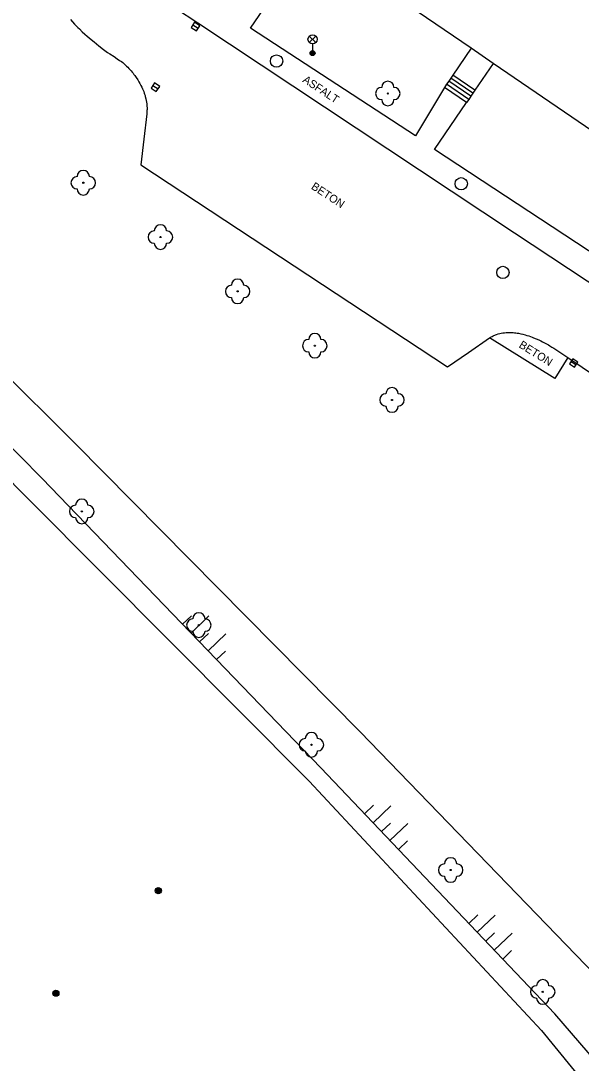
# Model space of a CAD drawing. Extents: x -539515 to -538098, y -1182060 to -1180157.
# Drawn here: x -538972.2 to -538926.7, y -1181508.2 to -1181423.5 of the extents above; entities that cross this region are included whole.
import ezdxf

# ---------------------------------------------------------------- set-up
doc = ezdxf.new("R2010")
doc.units = 0
for name, color, linetype in [('Vrstva 10', 7, 'Continuous'), ('Vrstva 11', 7, 'Continuous'), ('Vrstva 14', 7, 'Continuous'), ('Vrstva 15', 7, 'Continuous'), ('Vrstva 22', 7, 'Continuous'), ('Vrstva 23', 7, 'Continuous'), ('Vrstva 25', 7, 'Continuous'), ('Vrstva 27', 7, 'Continuous'), ('Vrstva 33', 7, 'Continuous'), ('Vrstva 40', 7, 'Continuous'), ('Vrstva 5', 7, 'Continuous')]:
    doc.layers.add(name, color=color, linetype=linetype)

msp = doc.modelspace()

# ---------------------------------------------------------------- linework, layer by layer
at = {"layer": 'Vrstva 10'}
for p, q in [((-538944.966, -1181432.217), (-538957.83, -1181423.69)), ((-538932.1, -1181440.742), (-538944.966, -1181432.217)), ((-538962.49, -1181435.19), (-538937.53, -1181451.61)), ((-538923.52, -1181446.42), (-538932.1, -1181440.742))]:
    msp.add_line(p, q, dxfattribs=at)
for points in [[(-538957.83, -1181423.69), (-538959.65, -1181422.485)], [(-538968.209, -1181423.401), (-538968.047, -1181423.582), (-538967.88, -1181423.76), (-538967.739, -1181423.904), (-538967.607, -1181424.036), (-538967.481, -1181424.158), (-538967.244, -1181424.379), (-538967.034, -1181424.568), (-538966.85, -1181424.73), (-538966.523, -1181425.007), (-538966.276, -1181425.211), (-538965.903, -1181425.514), (-538965.527, -1181425.817), (-538965.413, -1181425.906), (-538965.305, -1181425.986), (-538965.202, -1181426.057), (-538965.007, -1181426.187), (-538964.66, -1181426.407), (-538964.399, -1181426.574), (-538964.204, -1181426.706), (-538964.06, -1181426.811), (-538963.953, -1181426.894), (-538963.873, -1181426.959), (-538963.756, -1181427.061), (-538963.64, -1181427.17), (-538963.54, -1181427.271), (-538963.445, -1181427.37), (-538963.355, -1181427.468), (-538963.27, -1181427.565), (-538963.19, -1181427.66), (-538963.113, -1181427.753)], [(-538963.113, -1181427.753), (-538963.041, -1181427.845), (-538962.974, -1181427.935), (-538962.847, -1181428.112), (-538962.735, -1181428.281), (-538962.635, -1181428.442), (-538962.548, -1181428.596), (-538962.47, -1181428.741), (-538962.402, -1181428.879), (-538962.343, -1181429.01), (-538962.29, -1181429.133), (-538962.245, -1181429.25), (-538962.205, -1181429.36), (-538962.17, -1181429.463), (-538962.14, -1181429.561), (-538962.114, -1181429.652), (-538962.071, -1181429.825), (-538962.04, -1181429.977), (-538962.018, -1181430.111), (-538962.002, -1181430.228), (-538961.991, -1181430.33), (-538961.984, -1181430.42), (-538961.977, -1181430.577), (-538961.977, -1181430.696), (-538961.979, -1181430.784), (-538961.987, -1181430.917), (-538962, -1181431.05), (-538962.245, -1181433.12), (-538962.49, -1181435.19)], [(-538937.53, -1181451.61), (-538935.82, -1181450.435), (-538934.11, -1181449.26), (-538934.041, -1181449.215), (-538933.972, -1181449.172), (-538933.904, -1181449.134), (-538933.835, -1181449.098), (-538933.766, -1181449.064), (-538933.698, -1181449.034), (-538933.629, -1181449.006), (-538933.561, -1181448.981), (-538933.425, -1181448.936), (-538933.291, -1181448.9), (-538933.158, -1181448.872), (-538933.028, -1181448.85), (-538932.9, -1181448.834), (-538932.774, -1181448.823), (-538932.651, -1181448.817), (-538932.531, -1181448.816), (-538932.414, -1181448.817), (-538932.3, -1181448.823), (-538932.189, -1181448.831), (-538932.08, -1181448.841), (-538931.975, -1181448.854), (-538931.873, -1181448.869), (-538931.773, -1181448.885), (-538931.58, -1181448.922), (-538931.4, -1181448.964), (-538931.23, -1181449.008), (-538931.071, -1181449.054), (-538930.923, -1181449.101), (-538930.785, -1181449.147), (-538930.656, -1181449.194), (-538930.536, -1181449.24), (-538930.313, -1181449.331), (-538930.121, -1181449.415), (-538929.955, -1181449.493), (-538929.813, -1181449.563), (-538929.69, -1181449.626), (-538929.479, -1181449.74), (-538929.325, -1181449.828), (-538929.213, -1181449.895), (-538929.049, -1181449.997), (-538928.89, -1181450.1)], [(-538928.89, -1181450.1), (-538927.757, -1181450.856), (-538925.412, -1181452.42), (-538921.935, -1181454.74), (-538918.458, -1181457.06)]]:
    msp.add_lwpolyline(points, dxfattribs=at)
at = {"layer": 'Vrstva 11'}
for p, q in [((-538953.56, -1181424.08), (-538950.761, -1181419.977)), ((-538940.13, -1181432.83), (-538953.56, -1181424.08)), ((-538935.643, -1181429.63), (-538937.441, -1181428.404)), ((-538935.474, -1181429.382), (-538937.272, -1181428.156)), ((-538935.305, -1181429.134), (-538937.103, -1181427.908)), ((-538937.78, -1181428.9), (-538940.13, -1181432.83)), ((-538935.982, -1181430.126), (-538937.78, -1181428.9)), ((-538935.812, -1181429.878), (-538937.61, -1181428.652)), ((-538938.59, -1181433.95), (-538935.982, -1181430.126)), ((-538925.14, -1181442.78), (-538938.59, -1181433.95)), ((-538928.82, -1181452.56), (-538934.11, -1181449.26)), ((-538927.757, -1181450.856), (-538928.82, -1181452.56))]:
    msp.add_line(p, q, dxfattribs=at)
for points in [[(-538935.618, -1181425.73), (-538937.103, -1181427.908), (-538937.272, -1181428.156), (-538937.441, -1181428.404), (-538937.61, -1181428.652), (-538937.78, -1181428.9)], [(-538933.82, -1181426.956), (-538935.305, -1181429.134), (-538935.474, -1181429.382), (-538935.643, -1181429.63), (-538935.812, -1181429.878), (-538935.982, -1181430.126)]]:
    msp.add_lwpolyline(points, dxfattribs=at)
at = {"layer": 'Vrstva 14'}
for p, q in [((-538989.63, -1181436.2), (-538967.81, -1181457.83)), ((-538970.5, -1181460.68), (-538991.5, -1181439.46)), ((-538967.81, -1181457.83), (-538944.64, -1181481.26)), ((-538947.83, -1181484.2), (-538970.5, -1181460.68)), ((-538944.64, -1181481.26), (-538925.51, -1181501.02)), ((-538928.8, -1181504.18), (-538947.83, -1181484.2)), ((-538910.33, -1181525.69), (-538928.8, -1181504.18))]:
    msp.add_line(p, q, dxfattribs=at)
at = {"layer": 'Vrstva 15'}
for p, q in [((-538959.089, -1181472.519), (-538958.369, -1181471.825)), ((-538958.395, -1181473.239), (-538956.955, -1181471.851)), ((-538957.701, -1181473.959), (-538956.981, -1181473.265)), ((-538957.007, -1181474.679), (-538955.567, -1181473.291)), ((-538956.313, -1181475.399), (-538955.593, -1181474.705)), ((-538944.283, -1181487.924), (-538943.559, -1181487.234)), ((-538943.594, -1181488.648), (-538942.145, -1181487.269)), ((-538942.904, -1181489.372), (-538942.18, -1181488.682)), ((-538942.214, -1181490.096), (-538940.766, -1181488.717)), ((-538941.525, -1181490.82), (-538940.801, -1181490.131)), ((-538935.804, -1181496.826), (-538935.08, -1181496.136)), ((-538935.115, -1181497.55), (-538933.666, -1181496.171)), ((-538934.425, -1181498.274), (-538933.701, -1181497.584)), ((-538933.735, -1181498.998), (-538932.287, -1181497.619)), ((-538933.046, -1181499.722), (-538932.322, -1181499.033))]:
    msp.add_line(p, q, dxfattribs=at)
at = {"layer": 'Vrstva 22'}
for centre in [(-538942.39, -1181429.4), (-538967.16, -1181436.65), (-538960.882, -1181441.062), (-538954.605, -1181445.475), (-538948.328, -1181449.888), (-538942.05, -1181454.3), (-538967.28, -1181463.35), (-538957.76, -1181472.59), (-538948.6, -1181482.31), (-538937.28, -1181492.49), (-538929.79, -1181502.39)]:
    msp.add_circle(centre, 0.05, dxfattribs=at)
for centre, start, end in [((-538942.39, -1181428.9), 0, 180), ((-538942.89, -1181429.4), 90, 270), ((-538941.89, -1181429.4), 270, 90), ((-538942.39, -1181429.9), 180, 0), ((-538967.66, -1181436.65), 90, 270), ((-538967.16, -1181436.15), 0, 180), ((-538966.66, -1181436.65), 270, 90), ((-538967.16, -1181437.15), 180, 0), ((-538960.882, -1181440.562), 0, 180), ((-538961.382, -1181441.062), 90, 270), ((-538960.382, -1181441.062), 270, 90), ((-538960.882, -1181441.562), 180, 0), ((-538954.605, -1181444.975), 0, 180), ((-538955.105, -1181445.475), 90, 270), ((-538954.105, -1181445.475), 270, 90), ((-538954.605, -1181445.975), 180, 0), ((-538948.328, -1181449.388), 0, 180), ((-538948.828, -1181449.888), 90, 270), ((-538947.828, -1181449.888), 270, 90), ((-538948.328, -1181450.388), 180, 0), ((-538942.55, -1181454.3), 90, 270), ((-538942.05, -1181453.8), 0, 180), ((-538941.55, -1181454.3), 270, 90), ((-538942.05, -1181454.8), 180, 0), ((-538967.28, -1181462.85), 0, 180), ((-538967.78, -1181463.35), 90, 270), ((-538966.78, -1181463.35), 270, 90), ((-538967.28, -1181463.85), 180, 0), ((-538957.76, -1181472.09), 0, 180), ((-538958.26, -1181472.59), 90, 270), ((-538957.26, -1181472.59), 270, 90), ((-538957.76, -1181473.09), 180, 0), ((-538949.1, -1181482.31), 90, 270), ((-538948.6, -1181481.81), 0, 180), ((-538948.1, -1181482.31), 270, 90), ((-538948.6, -1181482.81), 180, 0), ((-538937.78, -1181492.49), 90, 270), ((-538937.28, -1181491.99), 0, 180), ((-538936.78, -1181492.49), 270, 90), ((-538937.28, -1181492.99), 180, 0), ((-538929.79, -1181501.89), 0, 180), ((-538930.29, -1181502.39), 90, 270), ((-538929.29, -1181502.39), 270, 90), ((-538929.79, -1181502.89), 180, 0)]:
    msp.add_arc(centre, 0.5, start, end, dxfattribs=at)
at = {"layer": 'Vrstva 23'}
for p, q in [((-538993.31, -1181440.59), (-538971.49, -1181462.49)), ((-538971.49, -1181462.49), (-538948.78, -1181485.26)), ((-538948.78, -1181485.26), (-538929.88, -1181505.52)), ((-538929.88, -1181505.52), (-538913.28, -1181525.86))]:
    msp.add_line(p, q, dxfattribs=at)
at = {"layer": 'Vrstva 25'}
for centre, radius in [((-538961.06, -1181494.17), 0.25), ((-538961.06, -1181494.17), 0.2), ((-538961.06, -1181494.17), 0.15), ((-538961.06, -1181494.17), 0.1), ((-538961.06, -1181494.17), 0.05), ((-538969.39, -1181502.5), 0.25), ((-538969.39, -1181502.5), 0.2), ((-538969.39, -1181502.5), 0.15), ((-538969.39, -1181502.5), 0.1), ((-538969.39, -1181502.5), 0.05)]:
    msp.add_circle(centre, radius, dxfattribs=at)
at = {"layer": 'Vrstva 27'}
for p, q in [((-538958.242, -1181423.823), (-538957.826, -1181424.099)), ((-538961.499, -1181428.753), (-538961.081, -1181429.027)), ((-538927.478, -1181451.161), (-538927.062, -1181451.439))]:
    msp.add_line(p, q, dxfattribs=at)
for points in [[(-538958.381, -1181424.031), (-538957.964, -1181424.308), (-538957.687, -1181423.891), (-538958.104, -1181423.614)], [(-538961.636, -1181428.961), (-538961.219, -1181429.236), (-538960.944, -1181428.819), (-538961.361, -1181428.544)], [(-538927.617, -1181451.369), (-538927.201, -1181451.647), (-538926.923, -1181451.231), (-538927.339, -1181450.953)]]:
    msp.add_lwpolyline(points, close=True, dxfattribs=at)
for centre in [(-538951.44, -1181426.76), (-538936.42, -1181436.73), (-538933.03, -1181443.94)]:
    msp.add_circle(centre, 0.5, dxfattribs=at)
at = {"layer": 'Vrstva 33'}
for p, q in [((-538948.775, -1181425.26), (-538948.245, -1181424.73)), ((-538948.775, -1181424.73), (-538948.245, -1181425.26)), ((-538948.51, -1181425.37), (-538948.51, -1181426.12))]:
    msp.add_line(p, q, dxfattribs=at)
for centre, radius in [((-538948.51, -1181424.995), 0.375), ((-538948.51, -1181426.12), 0.2), ((-538948.51, -1181426.12), 0.145), ((-538948.51, -1181426.12), 0.0876)]:
    msp.add_circle(centre, radius, dxfattribs=at)
at = {"layer": 'Vrstva 5'}
msp.add_lwpolyline([(-538912.8, -1181441.293), (-538918.981, -1181437.077), (-538920.514, -1181436.032), (-538933.82, -1181426.956), (-538935.618, -1181425.73), (-538948.631, -1181416.854), (-538950.43, -1181415.627), (-538957.77, -1181410.62)], dxfattribs=at)

# ---------------------------------------------------------------- texts
at = {"layer": 'Vrstva 40'}
for s, rotation, p in [('ASFALT', 326.45887, (-538949.373, -1181428.424)), ('BETON', 326.66098, (-538948.68, -1181437.105)), ('BETON', 328.04332, (-538931.787, -1181449.989))]:
    msp.add_text(s, height=0.65, rotation=rotation, dxfattribs=at).set_placement(p)

doc.saveas('drawing.dxf')
